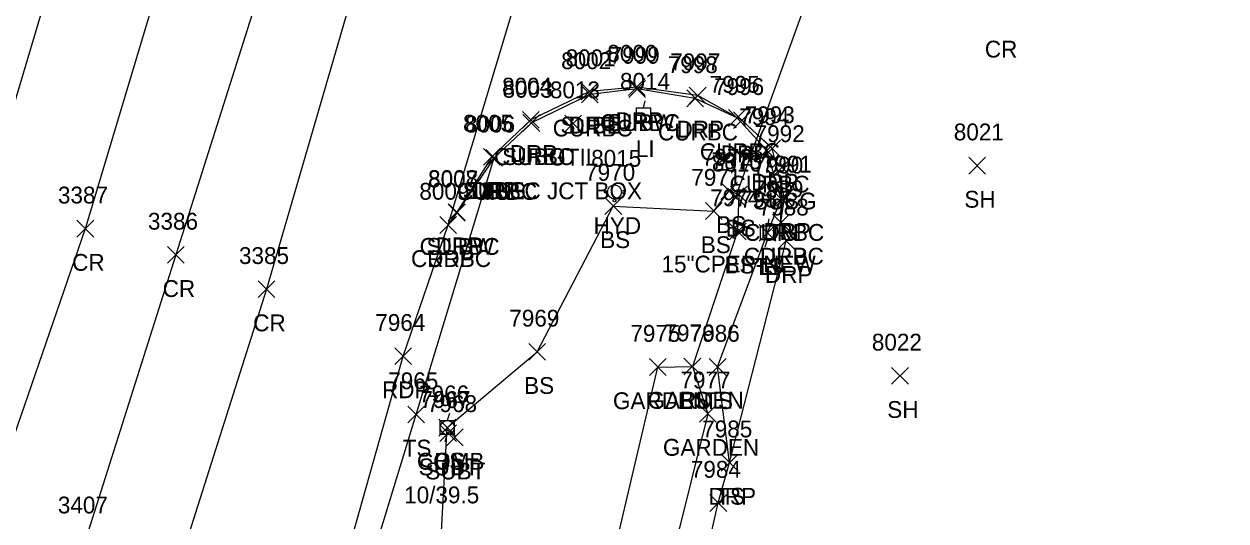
# Model space of a CAD drawing. Extents: x 1462089 to 1464015, y 730534 to 736144.
# Drawn here: x 1462973.1 to 1463115.9, y 732635.8 to 732694.9 of the extents above; entities that cross this region are included whole.
import ezdxf

# ---------------------------------------------------------------- set-up
doc = ezdxf.new("R2010")
doc.units = 0
for name, color, linetype in [('D_A', 7, 'Continuous'), ('D_C', 7, 'Continuous'), ('D_I', 7, 'Continuous'), ('D_TIC', 7, 'Continuous'), ('DCP', 7, 'Continuous'), ('L_A', 7, 'Continuous'), ('L_I', 7, 'Continuous'), ('L_TIC', 7, 'Continuous'), ('LAPB', 7, 'Continuous'), ('LELB', 7, 'Continuous'), ('P_A', 7, 'Continuous'), ('P_I', 7, 'Continuous'), ('P_TIC', 7, 'Continuous'), ('PET', 7, 'Continuous'), ('PRC', 7, 'Continuous'), ('R_A', 7, 'Continuous'), ('R_I', 7, 'Continuous'), ('R_TIC', 7, 'Continuous'), ('RC', 7, 'Continuous'), ('RDP', 7, 'Continuous'), ('U_A', 7, 'Continuous'), ('U_C', 7, 'Continuous'), ('U_I', 7, 'Continuous'), ('U_TIC', 7, 'Continuous'), ('UDEFAULT', 7, 'Continuous'), ('ULP', 7, 'Continuous'), ('UP', 7, 'Continuous'), ('UWFH', 7, 'Continuous')]:
    doc.layers.add(name, color=color, linetype=linetype)

msp = doc.modelspace()

# ---------------------------------------------------------------- linework, layer by layer
at = {"layer": 'D_TIC'}
for points in [[(1463056.68, 732673.35), (1463058.68, 732675.35)], [(1463058.68, 732673.35), (1463056.68, 732675.35)]]:
    msp.add_lwpolyline(points, dxfattribs=at)
at = {"layer": 'DCP'}
msp.add_lwpolyline([(1463057.68, 732674.35), (1463080.04, 732736.37)], dxfattribs=at)
at = {"layer": 'L_TIC'}
for points in [[(1463027.95, 732677.98), (1463029.95, 732679.98)], [(1463029.95, 732677.98), (1463027.95, 732679.98)], [(1463085.34, 732677.05), (1463087.34, 732679.05)], [(1463087.34, 732677.05), (1463085.34, 732679.05)], [(1463055.88, 732674.04), (1463057.88, 732676.04)], [(1463057.88, 732674.04), (1463055.88, 732676.04)], [(1463042.1, 732672.25), (1463044.1, 732674.25)], [(1463044.1, 732672.25), (1463042.1, 732674.25)], [(1463057.02, 732673.62), (1463059.02, 732675.62)], [(1463059.02, 732673.62), (1463057.02, 732675.62)], [(1463062.07, 732673.11), (1463064.07, 732675.11)], [(1463064.07, 732673.11), (1463062.07, 732675.11)], [(1463054.06, 732671.65), (1463056.06, 732673.65)], [(1463056.06, 732671.65), (1463054.06, 732673.65)], [(1463056.88, 732669.23), (1463058.88, 732671.23)], [(1463058.88, 732669.23), (1463056.88, 732671.23)], [(1463060.42, 732669.06), (1463062.42, 732671.06)], [(1463062.42, 732669.06), (1463060.42, 732671.06)], [(1463033.06, 732654.92), (1463035.06, 732656.92)], [(1463035.06, 732654.92), (1463033.06, 732656.92)], [(1463047.39, 732653.11), (1463049.39, 732655.11)], [(1463049.39, 732653.11), (1463047.39, 732655.11)], [(1463051.5, 732653.17), (1463053.5, 732655.17)], [(1463053.5, 732653.17), (1463051.5, 732655.17)], [(1463051.5, 732653.17), (1463053.5, 732655.17)], [(1463053.5, 732653.17), (1463051.5, 732655.17)], [(1463054.5, 732653.12), (1463056.5, 732655.12)], [(1463056.5, 732653.12), (1463054.5, 732655.12)], [(1463076.17, 732652.07), (1463078.17, 732654.07)], [(1463078.17, 732652.07), (1463076.17, 732654.07)], [(1463018.66, 732647.48), (1463020.66, 732649.48)], [(1463020.66, 732647.48), (1463018.66, 732649.48)], [(1463053.33, 732647.57), (1463055.33, 732649.57)], [(1463055.33, 732647.57), (1463053.33, 732649.57)], [(1463022.37, 732645.92), (1463024.37, 732647.92)], [(1463024.37, 732645.92), (1463022.37, 732647.92)], [(1463022.37, 732645.92), (1463024.37, 732647.92)], [(1463024.37, 732645.92), (1463022.37, 732647.92)], [(1463055.93, 732641.76), (1463057.93, 732643.76)], [(1463057.93, 732641.76), (1463055.93, 732643.76)]]:
    msp.add_lwpolyline(points, dxfattribs=at)
at = {"layer": 'LAPB'}
msp.add_lwpolyline([(1463039.88, 732526.33), (1463032.83, 732537.24), (1463025.77, 732549.01), (1463027.29, 732562.25), (1463031, 732585.6), (1463040.5, 732620.6), (1463048.39, 732654.11), (1463052.5, 732654.17), (1463054.33, 732648.57), (1463048.28, 732624.19), (1463040.98, 732596.29), (1463035.52, 732567.9), (1463038.13, 732549.55), (1463046.96, 732533.3)], dxfattribs=at)
at = {"layer": 'LELB'}
for points in [[(1462979.33, 732416.63), (1462961.36, 732420.17), (1462955.85, 732428.74), (1462956.29, 732434.85), (1462966.76, 732463.68), (1462980.6, 732511.47), (1462984.53, 732526.39), (1462991.81, 732550.75), (1463002.8, 732585.8), (1463012.99, 732626.57), (1463019.66, 732648.48), (1463028.95, 732678.98)], [(1463088.41, 732356.64), (1463069.15, 732364.7), (1463042.09, 732374.68), (1463015.52, 732382.44), (1462985.91, 732395.79), (1462980.43, 732411.77), (1462979.33, 732416.63), (1462980.44, 732426.24), (1462963.11, 732427.49), (1462964.06, 732433.7), (1462973.06, 732458.07), (1462983.46, 732499.39), (1462986.26, 732526.46), (1462994.89, 732549.29), (1463007.25, 732585.8), (1463022.01, 732622.27), (1463023.37, 732646.92), (1463034.06, 732655.92), (1463043.1, 732673.25), (1463055.06, 732672.65), (1463056.88, 732675.04), (1463058.02, 732674.62), (1463057.88, 732670.23), (1463052.5, 732654.17)], [(1463056.93, 732642.76), (1463055.5, 732654.12), (1463061.42, 732670.06), (1463063.07, 732674.11)]]:
    msp.add_lwpolyline(points, dxfattribs=at)
at = {"layer": 'P_TIC'}
for points in [[(1462979.34, 732669.55), (1462981.34, 732671.55)], [(1462981.34, 732669.55), (1462979.34, 732671.55)], [(1463022.48, 732670), (1463024.48, 732672)], [(1463024.48, 732670), (1463022.48, 732672)], [(1462990.11, 732666.44), (1462992.11, 732668.44)], [(1462992.11, 732666.44), (1462990.11, 732668.44)], [(1463000.87, 732662.36), (1463002.87, 732664.36)], [(1463002.87, 732662.36), (1463000.87, 732664.36)], [(1463017.12, 732654.41), (1463019.12, 732656.41)], [(1463019.12, 732654.41), (1463017.12, 732656.41)]]:
    msp.add_lwpolyline(points, dxfattribs=at)
at = {"layer": 'PET'}
msp.add_lwpolyline([(1462879.39, 732206.83), (1462892.22, 732254.3), (1462907.58, 732309.88), (1462913.99, 732337.71), (1462917.6, 732346.71), (1462929.48, 732377.39), (1462933.76, 732389.86), (1462941.67, 732414.76), (1462948.84, 732435.88), (1462965.82, 732486.16), (1462974.32, 732513.6), (1462985.99, 732551.34), (1462997.31, 732587.46), (1463010.57, 732628.54), (1463018.12, 732655.41), (1463023.48, 732671), (1463036.19, 732713.31)], dxfattribs=at)
at = {"layer": 'PRC'}
for points in [[(1463184.26, 733428.99), (1463177.5, 733386.21), (1463169.42, 733335), (1463162.87, 733301.13), (1463154.54, 733254.52), (1463145.29, 733216.48), (1463131.67, 733162.65), (1463112.82, 733093.24), (1463099.08, 733044.74), (1463082.5, 732993.09), (1463066.93, 732944.79), (1463054.22, 732905.14), (1463038.5, 732856.13), (1463025.08, 732814.55), (1463009.9, 732766.25), (1462997.49, 732727.73), (1462980.34, 732670.55), (1462968.82, 732637.25), (1462956.14, 732592.49), (1462943.23, 732555.63), (1462933.85, 732526.13), (1462921.41, 732485.16), (1462905.69, 732440.94), (1462895.98, 732404.53)], [(1463173.56, 733299.02), (1463165.51, 733252.57), (1463157.36, 733210.85), (1463147.48, 733159.84), (1463128.56, 733086.33), (1463116.13, 733039.22), (1463100.45, 732983.58), (1463087.95, 732938.84), (1463073.8, 732896.76), (1463059.6, 732849.78), (1463047.56, 732806.21), (1463032.36, 732758.17), (1463016.83, 732714.7), (1463001.87, 732663.36), (1462991.08, 732629.32), (1462977.35, 732584.7), (1462966.06, 732548.54), (1462956.48, 732518.6), (1462941.54, 732474.04), (1462928.1, 732429.75), (1462916.12, 732396.98)], [(1463154.54, 733254.52), (1463146.61, 733215.85), (1463135.44, 733161.47), (1463118.39, 733090.76), (1463105.83, 733042.87), (1463089.37, 732989.24), (1463076.43, 732943.44), (1463063.88, 732901.54), (1463049.78, 732852.76), (1463036.58, 732810.58), (1463021.66, 732763.56), (1463007.35, 732718.7), (1462991.11, 732667.44), (1462980.42, 732633.72), (1462966.43, 732588.15), (1462955.05, 732551.99), (1462945.51, 732521.94), (1462931.54, 732478.17), (1462917.14, 732435.42), (1462906.01, 732400.46)], [(1462985.72, 732731.93), (1462969.44, 732677.27), (1462957.49, 732641.21), (1462943.9, 732597.67), (1462931.65, 732559.61), (1462922.76, 732531.12), (1462910.18, 732489.03), (1462895.07, 732444.4), (1462885.16, 732408.13), (1462864.59, 732375.33), (1462853.42, 732347.26), (1462832.87, 732276.65), (1462823.23, 732232.91), (1462808.46, 732182.81), (1462796.54, 732136.82), (1462784.67, 732094.48), (1462773.76, 732052.9), (1462761.07, 732007.23), (1462748.95, 731961.52), (1462736.51, 731921.31)]]:
    msp.add_lwpolyline(points, dxfattribs=at)
at = {"layer": 'R_TIC'}
for points in [[(1463039.28, 732685.86), (1463041.28, 732687.86)], [(1463041.28, 732685.86), (1463039.28, 732687.86)], [(1463039.31, 732685.51), (1463041.31, 732687.51)], [(1463041.31, 732685.51), (1463039.31, 732687.51)], [(1463044.89, 732686.39), (1463046.89, 732688.39)], [(1463046.89, 732686.39), (1463044.89, 732688.39)], [(1463044.94, 732686.16), (1463046.94, 732688.16)], [(1463046.94, 732686.16), (1463044.94, 732688.16)], [(1463052.13, 732685.38), (1463054.13, 732687.38)], [(1463054.13, 732685.38), (1463052.13, 732687.38)], [(1463051.83, 732685.04), (1463053.83, 732687.04)], [(1463053.83, 732685.04), (1463051.83, 732687.04)], [(1463032.3, 732682.49), (1463034.3, 732684.49)], [(1463034.3, 732682.49), (1463032.3, 732684.49)], [(1463056.81, 732682.71), (1463058.81, 732684.71)], [(1463058.81, 732682.71), (1463056.81, 732684.71)], [(1463057.39, 732682.44), (1463059.39, 732684.44)], [(1463059.39, 732682.44), (1463057.39, 732684.44)], [(1463032.36, 732682.12), (1463034.36, 732684.12)], [(1463034.36, 732682.12), (1463032.36, 732684.12)], [(1463027.66, 732678.09), (1463029.66, 732680.09)], [(1463029.66, 732678.09), (1463027.66, 732680.09)], [(1463027.95, 732677.98), (1463029.95, 732679.98)], [(1463029.95, 732677.98), (1463027.95, 732679.98)], [(1463060.33, 732678.85), (1463062.33, 732680.85)], [(1463062.33, 732678.85), (1463060.33, 732680.85)], [(1463060.98, 732679.09), (1463062.98, 732681.09)], [(1463062.98, 732679.09), (1463060.98, 732681.09)], [(1463062.07, 732673.11), (1463064.07, 732675.11)], [(1463064.07, 732673.11), (1463062.07, 732675.11)], [(1463062.45, 732673.22), (1463064.45, 732675.22)], [(1463064.45, 732673.22), (1463062.45, 732675.22)], [(1463023.49, 732671.45), (1463025.49, 732673.45)], [(1463025.49, 732671.45), (1463023.49, 732673.45)], [(1463023.5, 732671.51), (1463025.5, 732673.51)], [(1463025.5, 732671.51), (1463023.5, 732673.51)], [(1463022.48, 732670), (1463024.48, 732672)], [(1463024.48, 732670), (1463022.48, 732672)], [(1463022.48, 732670), (1463024.48, 732672)], [(1463024.48, 732670), (1463022.48, 732672)], [(1463062.03, 732670.29), (1463064.03, 732672.29)], [(1463064.03, 732670.29), (1463062.03, 732672.29)], [(1463062.03, 732670.29), (1463064.03, 732672.29)], [(1463064.03, 732670.29), (1463062.03, 732672.29)], [(1463062.64, 732668.12), (1463064.64, 732670.12)], [(1463064.64, 732668.12), (1463062.64, 732670.12)], [(1463055.93, 732641.76), (1463057.93, 732643.76)], [(1463057.93, 732641.76), (1463055.93, 732643.76)], [(1463054.58, 732636.96), (1463056.58, 732638.96)], [(1463056.58, 732636.96), (1463054.58, 732638.96)]]:
    msp.add_lwpolyline(points, dxfattribs=at)
at = {"layer": 'RC'}
msp.add_lwpolyline([(1463063.03, 732671.29), (1463063.07, 732674.11), (1463061.33, 732679.85), (1463057.81, 732683.71), (1463052.83, 732686.04), (1463045.94, 732687.16), (1463040.31, 732686.51), (1463033.36, 732683.12), (1463028.95, 732678.98), (1463024.49, 732672.45), (1463023.48, 732671)], dxfattribs=at)
at = {"layer": 'RDP'}
msp.add_lwpolyline([(1463048.56, 732539.06), (1463047.73, 732603.27), (1463055.58, 732637.96), (1463056.93, 732642.76), (1463063.64, 732669.12), (1463063.03, 732671.29), (1463063.45, 732674.22), (1463061.98, 732680.09), (1463058.39, 732683.44), (1463053.13, 732686.38), (1463045.89, 732687.39), (1463040.28, 732686.86), (1463033.3, 732683.49), (1463028.66, 732679.09), (1463024.5, 732672.51), (1463023.48, 732671)], dxfattribs=at)
at = {"layer": 'U_TIC'}
for points in [[(1463039.28, 732685.86), (1463041.28, 732687.86)], [(1463041.28, 732685.86), (1463039.28, 732687.86)], [(1463044.94, 732686.16), (1463046.94, 732688.16)], [(1463046.94, 732686.16), (1463044.94, 732688.16)], [(1463032.36, 732682.12), (1463034.36, 732684.12)], [(1463034.36, 732682.12), (1463032.36, 732684.12)], [(1463027.66, 732678.09), (1463029.66, 732680.09)], [(1463029.66, 732678.09), (1463027.66, 732680.09)], [(1463062.16, 732676.84), (1463064.16, 732678.84)], [(1463064.16, 732676.84), (1463062.16, 732678.84)], [(1463023.49, 732671.45), (1463025.49, 732673.45)], [(1463025.49, 732671.45), (1463023.49, 732673.45)], [(1463022.47, 732645.25), (1463024.47, 732647.25)], [(1463024.47, 732645.25), (1463022.47, 732647.25)], [(1463023.26, 732644.76), (1463025.26, 732646.76)], [(1463025.26, 732644.76), (1463023.26, 732646.76)]]:
    msp.add_lwpolyline(points, dxfattribs=at)
at = {"layer": 'UDEFAULT'}
for points in [[(1463037.34, 732682.05), (1463039.34, 732684.05)], [(1463039.34, 732682.05), (1463037.34, 732684.05)]]:
    msp.add_lwpolyline(points, dxfattribs=at)
at = {"layer": 'ULP'}
for p, q in [((1463046.84, 732685.73), (1463046.67, 732684.9)), ((1463045.84, 732683.23), (1463045.84, 732684.9)), ((1463045.84, 732684.9), (1463047.51, 732684.9)), ((1463047.51, 732684.9), (1463047.51, 732683.23)), ((1463047.51, 732683.23), (1463045.84, 732683.23)), ((1463046.42, 732682.4), (1463046.67, 732683.23)), ((1463046.67, 732684.06), (1463046.67, 732684.06)), ((1463061.58, 732671.73), (1463061.42, 732670.9)), ((1463060.58, 732669.23), (1463060.58, 732670.9)), ((1463060.58, 732670.9), (1463062.25, 732670.9)), ((1463061.42, 732670.06), (1463061.42, 732670.06)), ((1463062.25, 732670.9), (1463062.25, 732669.23)), ((1463062.25, 732669.23), (1463060.58, 732669.23)), ((1463061.17, 732668.4), (1463061.42, 732669.23))]:
    msp.add_line(p, q, dxfattribs=at)
at = {"layer": 'UP'}
for p, q in [((1463023.62, 732648.59), (1463023.37, 732647.75)), ((1463022.54, 732646.09), (1463022.54, 732647.75)), ((1463022.54, 732647.75), (1463024.2, 732647.75)), ((1463024.2, 732647.75), (1463024.2, 732646.09)), ((1463024.2, 732646.09), (1463022.54, 732646.09)), ((1463023.12, 732645.25), (1463023.37, 732646.09)), ((1463023.37, 732646.92), (1463023.37, 732646.92))]:
    msp.add_line(p, q, dxfattribs=at)
msp.add_circle((1463023.37, 732646.92), 0.833, dxfattribs=at)
at = {"layer": 'UWFH'}
msp.add_line((1463043.24, 732674.92), (1463043.24, 732674.92), dxfattribs=at)
for centre, radius in [((1463043.24, 732674.92), 0.833), ((1463042.24, 732674.92), 0.167), ((1463044.24, 732674.92), 0.167), ((1463043.24, 732673.92), 0.167)]:
    msp.add_circle(centre, radius, dxfattribs=at)

# ---------------------------------------------------------------- texts
at = {"layer": 'D_A'}
msp.add_text('P', height=2, dxfattribs=at).set_placement((1463057.06, 732669.35))
at = {"layer": 'D_C'}
msp.add_text('15"CPEP-NEW', height=2, dxfattribs=at).set_placement((1463048.83, 732665.35))
at = {"layer": 'D_I'}
msp.add_text('8010', height=2, dxfattribs=at).set_placement((1463054.82, 732677.35))
at = {"layer": 'L_A'}
for s, p in [('TS', (1463027.36, 732673.98)), ('SH', (1463084.83, 732673.05)), ('BS', (1463055.33, 732670.04)), ('BS', (1463056.46, 732669.62)), ('BS', (1463041.54, 732668.25)), ('TS', (1463061.48, 732669.11)), ('BS', (1463053.5, 732667.65)), ('BS', (1463056.32, 732665.23)), ('TS', (1463059.83, 732665.06)), ('BS', (1463032.5, 732650.92)), ('GARDEN', (1463043.06, 732649.11)), ('GARDEN', (1463047.17, 732649.17)), ('BS', (1463050.95, 732649.17)), ('TS', (1463053.91, 732649.12)), ('SH', (1463075.66, 732648.07)), ('TS', (1463018.07, 732643.48)), ('GARDEN', (1463049, 732643.57)), ('CS', (1463021.81, 732641.92)), ('BS', (1463021.81, 732641.92)), ('TS', (1463055.34, 732637.76))]:
    msp.add_text(s, height=2, dxfattribs=at).set_placement(p)
at = {"layer": 'L_I'}
for s, p in [('8006', (1463025.48, 732681.98)), ('8021', (1463083.57, 732681.05)), ('7972', (1463053.63, 732678.04)), ('7973', (1463054.76, 732677.62)), ('7990', (1463059.73, 732677.11)), ('7970', (1463039.75, 732676.25)), ('7971', (1463052.37, 732675.65)), ('7974', (1463054.62, 732673.23)), ('7987', (1463058.16, 732673.06)), ('7969', (1463030.74, 732658.92)), ('7975', (1463045.13, 732657.11)), ('7976', (1463049.19, 732657.17)), ('7976', (1463049.19, 732657.17)), ('7986', (1463052.18, 732657.12)), ('8022', (1463073.83, 732656.07)), ('7965', (1463016.35, 732651.48)), ('7977', (1463051.08, 732651.57)), ('7966', (1463020.01, 732649.92)), ('7966', (1463020.01, 732649.92)), ('7985', (1463053.67, 732645.76))]:
    msp.add_text(s, height=2, dxfattribs=at).set_placement(p)
at = {"layer": 'P_A'}
for s, p in [('CR', (1463087.26, 732690.89)), ('CR', (1462978.78, 732665.55)), ('RDP', (1463020.97, 732666)), ('CR', (1462989.54, 732662.44)), ('CR', (1463000.3, 732658.36)), ('RDP', (1463015.61, 732650.41))]:
    msp.add_text(s, height=2, dxfattribs=at).set_placement(p)
at = {"layer": 'P_I'}
for s, p in [('8009', (1463020.05, 732674)), ('3387', (1462977.09, 732673.55)), ('3386', (1462987.79, 732670.44)), ('3385', (1462998.61, 732666.36)), ('7964', (1463014.81, 732658.41)), ('3407', (1462977.08, 732636.72))]:
    msp.add_text(s, height=2, dxfattribs=at).set_placement(p)
at = {"layer": 'R_A'}
for s, p in [('DRP', (1463043.38, 732682.39)), ('CURBC', (1463035.9, 732681.51)), ('DRP', (1463037.77, 732681.86)), ('CURBC', (1463041.52, 732682.16)), ('CURBC', (1463048.41, 732681.04)), ('DRP', (1463050.62, 732681.38)), ('CURBC', (1463028.94, 732678.12)), ('DRP', (1463030.79, 732678.49)), ('CURBC', (1463053.39, 732678.71)), ('DRP', (1463055.88, 732678.44)), ('CURBC', (1463024.54, 732673.98)), ('DRP', (1463026.15, 732674.09)), ('CURBC', (1463056.92, 732674.85)), ('DRP', (1463059.47, 732675.09)), ('CURBC', (1463058.66, 732669.11)), ('DRP', (1463060.94, 732669.22)), ('CURBC', (1463020.08, 732667.45)), ('DRP', (1463021.99, 732667.51)), ('CURBC', (1463019.06, 732666)), ('DRP', (1463020.97, 732666)), ('CURBC', (1463058.61, 732666.29)), ('DRP', (1463060.52, 732666.29)), ('DRP', (1463061.13, 732664.12)), ('DRP', (1463054.42, 732637.76))]:
    msp.add_text(s, height=2, dxfattribs=at).set_placement(p)
at = {"layer": 'R_I'}
for s, p in [('8002', (1463036.9, 732689.51)), ('8001', (1463037.43, 732689.86)), ('8000', (1463042.39, 732690.39)), ('7999', (1463042.67, 732690.16)), ('7997', (1463049.87, 732689.38)), ('7998', (1463049.57, 732689.04)), ('7995', (1463054.55, 732686.71)), ('8004', (1463029.88, 732686.49)), ('8003', (1463029.94, 732686.12)), ('7996', (1463055.08, 732686.44)), ('7994', (1463058.07, 732682.85)), ('7993', (1463058.72, 732683.09)), ('8005', (1463025.24, 732682.09)), ('8006', (1463025.48, 732681.98)), ('7990', (1463059.73, 732677.11)), ('7991', (1463060.76, 732677.22)), ('8007', (1463021.08, 732675.45)), ('8008', (1463021.09, 732675.51)), ('8009', (1463020.05, 732674)), ('8009', (1463020.05, 732674)), ('7989', (1463059.76, 732674.29)), ('7989', (1463059.76, 732674.29)), ('7988', (1463060.38, 732672.12)), ('7985', (1463053.67, 732645.76)), ('7984', (1463052.32, 732640.96))]:
    msp.add_text(s, height=2, dxfattribs=at).set_placement(p)
at = {"layer": 'U_A'}
for s, p in [('SUBE', (1463036.82, 732681.86)), ('SUBW', (1463042.35, 732682.16)), ('SUBG', (1463029.89, 732678.12)), ('UTIL', (1463035.51, 732678.05)), ('LI', (1463045.78, 732679.06)), ('SUBG', (1463025.19, 732674.09)), ('SUBG', (1463059.69, 732672.84)), ('HYD', (1463040.76, 732669.92)), ('SUBW', (1463020.9, 732667.45)), ('LI', (1463060.52, 732665.06)), ('COMB', (1463019.76, 732641.92)), ('SUBT', (1463019.97, 732641.25)), ('SUBT', (1463020.76, 732640.76))]:
    msp.add_text(s, height=2, dxfattribs=at).set_placement(p)
at = {"layer": 'U_C'}
for s, p in [('ELEC JCT BOX', (1463027.49, 732674.05)), ('10/39.5', (1463018.24, 732637.92))]:
    msp.add_text(s, height=2, dxfattribs=at).set_placement(p)
at = {"layer": 'U_I'}
for s, p in [('8001', (1463037.43, 732689.86)), ('7999', (1463042.67, 732690.16)), ('8014', (1463043.9, 732687.06)), ('8003', (1463029.94, 732686.12)), ('8013', (1463035.57, 732686.05)), ('8005', (1463025.24, 732682.09)), ('7992', (1463059.9, 732680.84)), ('8015', (1463040.47, 732677.92)), ('8007', (1463021.08, 732675.45)), ('7987', (1463058.16, 732673.06)), ('7966', (1463020.01, 732649.92)), ('7967', (1463020.17, 732649.25)), ('7968', (1463020.96, 732648.76))]:
    msp.add_text(s, height=2, dxfattribs=at).set_placement(p)

doc.saveas('drawing.dxf')
